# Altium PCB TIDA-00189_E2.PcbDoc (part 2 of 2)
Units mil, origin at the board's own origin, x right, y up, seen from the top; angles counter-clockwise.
Board outline 2350 x 1950 mil, 4 copper layers (Layer 1 - Top Layer, Layer 2 - GND, Layer 3 - Inner Layer, Layer 4 - Bottom Layer), stack 61.4 mil thick; 163 components, 96 nets, 412 pads, 169 vias.
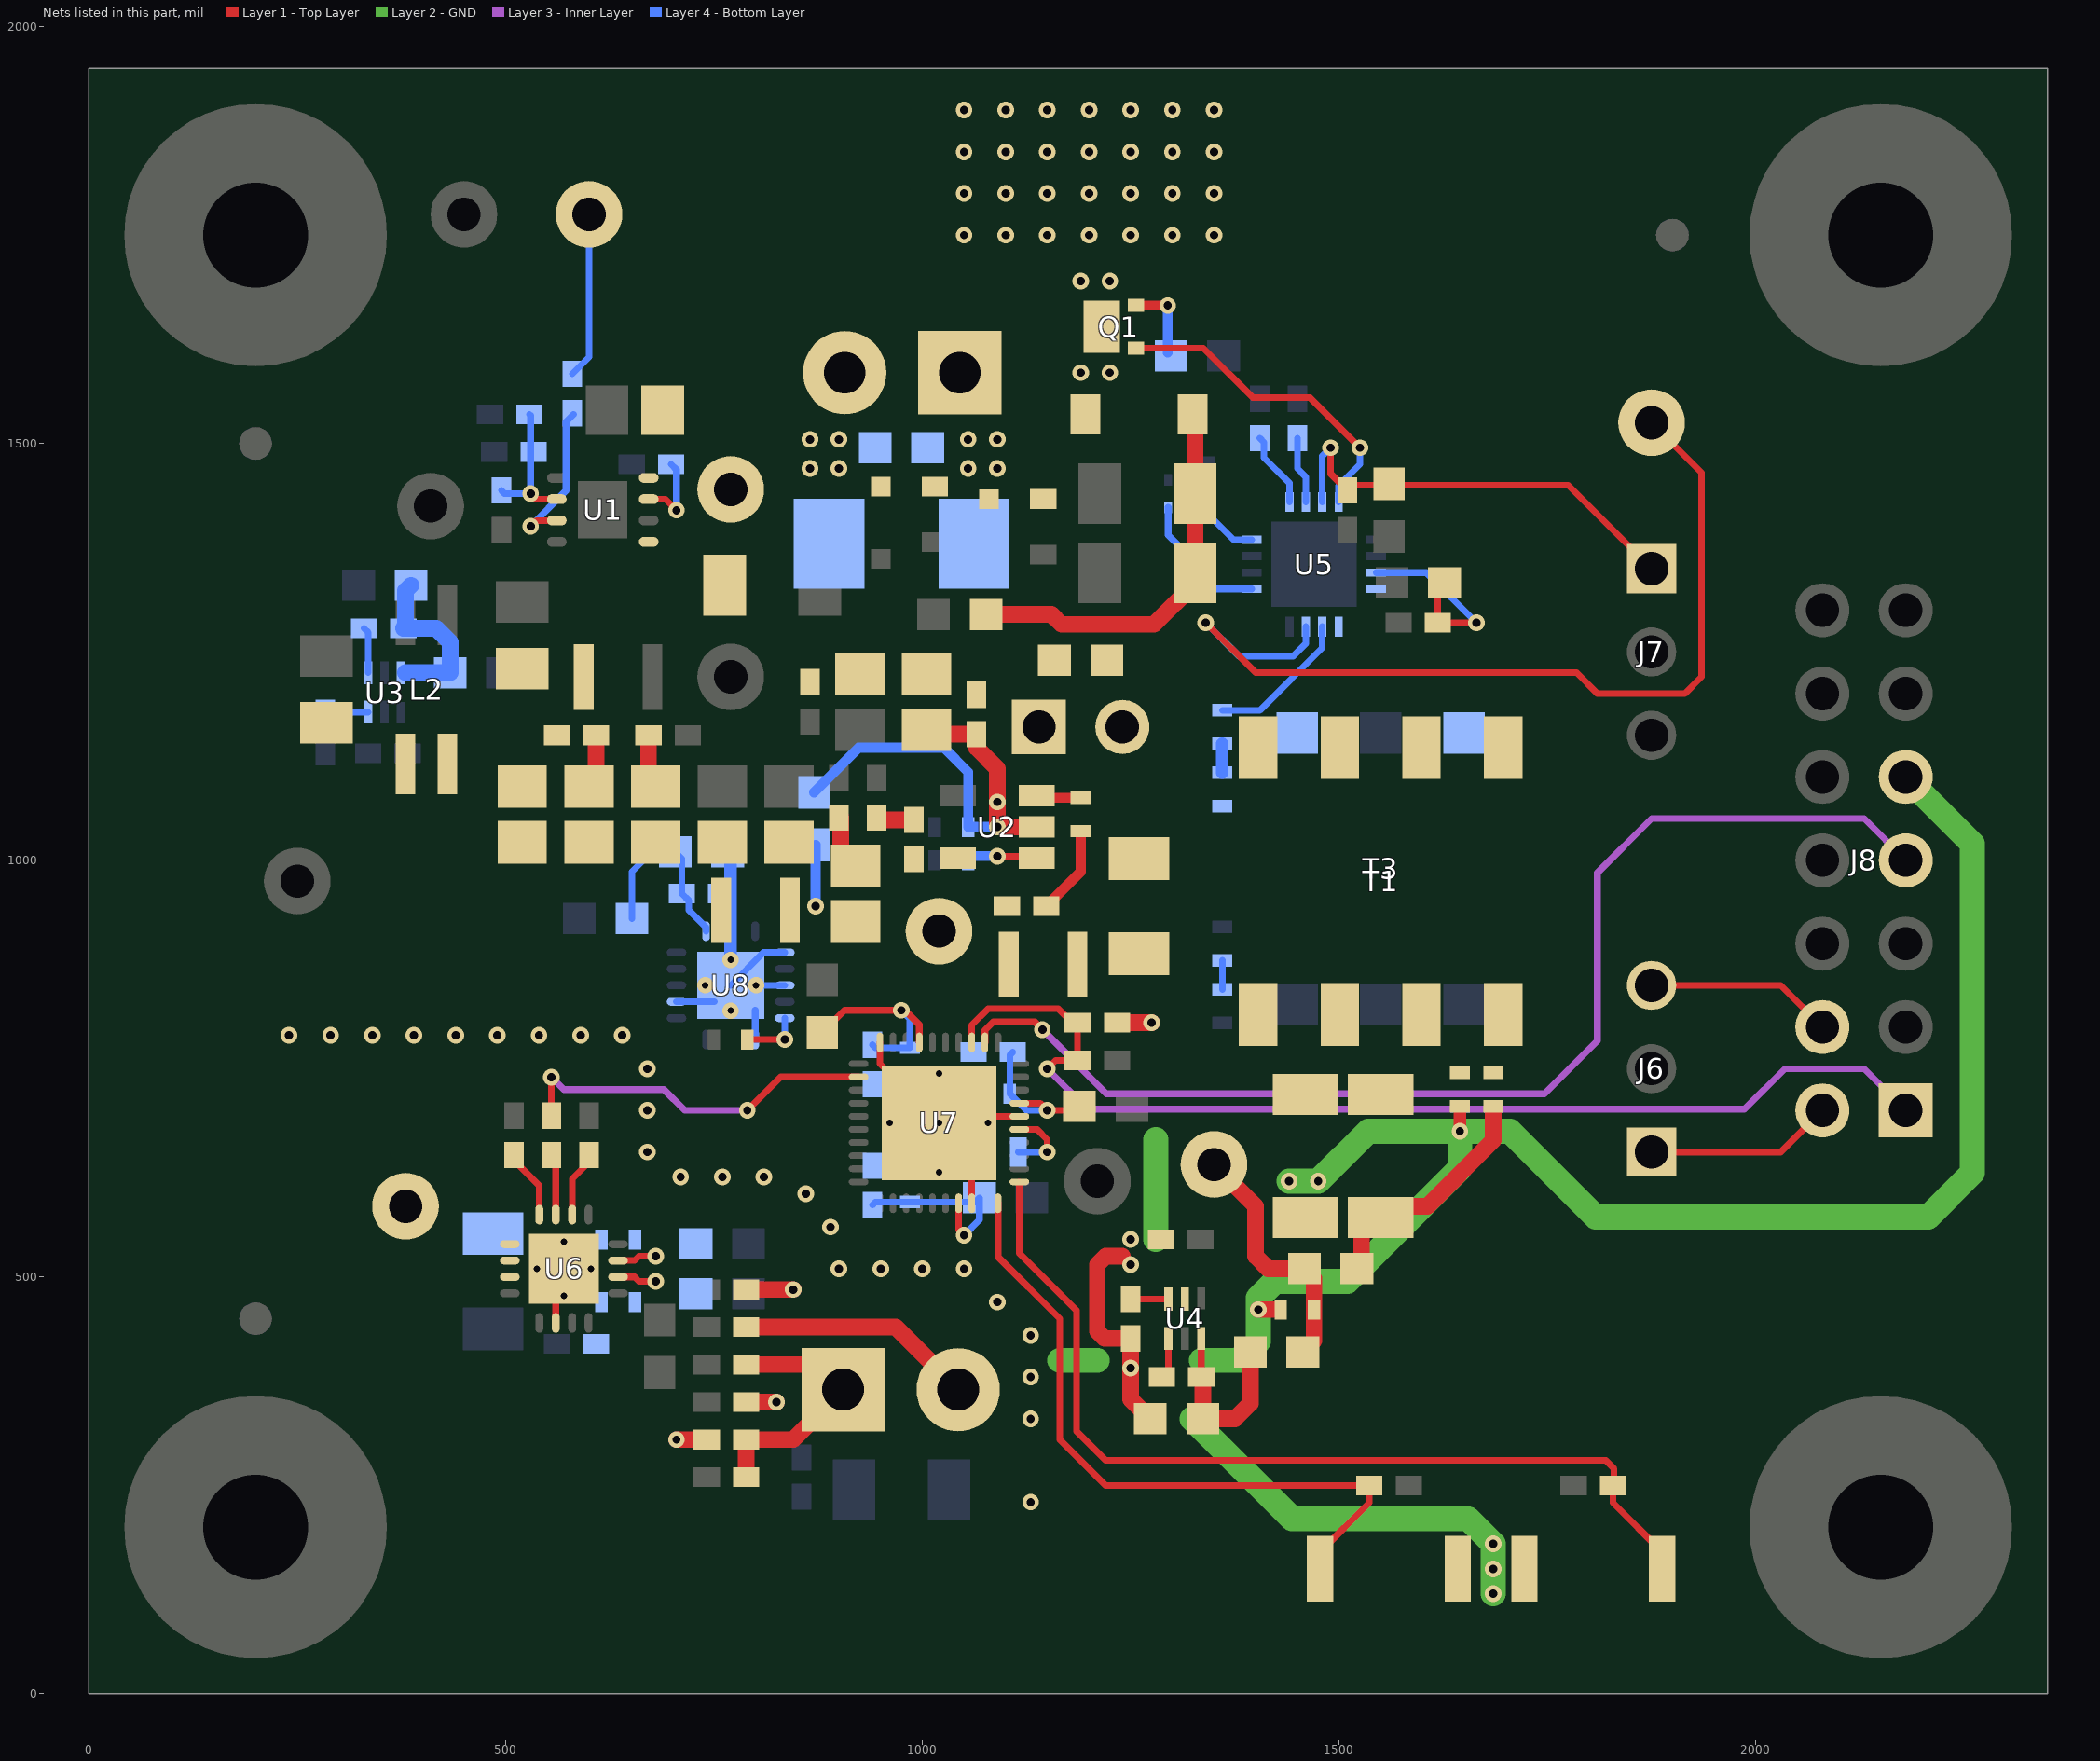
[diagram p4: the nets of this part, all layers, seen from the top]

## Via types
v1: diameter 20, hole 10, Layer 1 - Top Layer to Layer 4 - Bottom Layer, 147 vias
v2: diameter 19.68, hole 7.87, Layer 1 - Top Layer to Layer 4 - Bottom Layer, 22 vias

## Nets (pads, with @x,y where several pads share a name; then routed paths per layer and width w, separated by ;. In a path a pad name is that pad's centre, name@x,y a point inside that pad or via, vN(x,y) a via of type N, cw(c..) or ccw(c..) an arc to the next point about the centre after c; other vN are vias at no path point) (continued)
NetC1_2: C1.2 R4.1 R8.2 U1.2 | length 166.2
  Layer 1 - Top Layer w8: v1(530,1440) 536.76,1433.24 U1.2@561.36,1433.24
  Layer 4 - Bottom Layer w8: R8.2@495,1443.62 498.62,1440 v1(530,1440) 530,1490 530,1533.62 C1.2@528.62,1535
NetC2_1: C2.1 C3.1 C8.1 C9.1 L1.1 L2.3 R2.2
NetC2_2: C2.2 R5.2 | length 65.1
  Layer 1 - Top Layer w20: C2.2@600,1088.46 608.62,1097.09 R5.2@608.62,1150
NetC3_2: C3.2 R6.2 | length 65.1
  Layer 1 - Top Layer w20: R6.2@671.38,1150 671.38,1097.09 C3.2@680,1088.46
NetC4_2: C4.2 R7.2 | length 51.4
  Layer 1 - Top Layer w20: C4.2@902,1000 R7.2@902,1051.38
NetC5_1: C5.1 R1.2 TP1.1 U1.5 U1.8
NetC6_1: C6.1 D1.2 D3.2 D4.1 J1.2
  other v1: 865,1470 900,1470 865,1505 900,1505
NetC6_2: C6.2 D2.2 D3.1 D5.1 J1.1
  other v1: 1055,1470 1090,1470 1055,1505 1090,1505
NetC8_2: C8.2 L2.4 L3.1 R5.1 R9.2
NetC11_1: C11.1 U1.7 | length 96.5
  Layer 1 - Top Layer w8: U1.7@671.6,1433.24 691.76,1433.24 v1(705,1420)
  Layer 4 - Bottom Layer w8: C11.1@698.62,1475 705,1468.62 v1(705,1420)
NetC12_1: C12.1 C16.1 R10.2 R15.2 U2.2 | length 581.2
  Layer 1 - Top Layer w20: C12.1@1005,1156.54 1010.16,1151.38 R10.2@1065,1151.38 1065,1135 1090,1110 v1(1090,1040) U2.2@1137.24,1040
  Layer 4 - Bottom Layer w12: R15.2@870,1081.5 923.5,1135 1025.87,1135 1055,1105.87 C16.1@1055,1040 v1(1090,1040) v1(1090,1070)
NetC12_2: C12.2 C15.1 J2.1 R10.1 R12.2 R13.2
NetC13_1: C13.1 R11.2 | length 107.1
  Layer 1 - Top Layer w12: C13.1@1148.62,945 1190,986.38 R11.2@1190,1035
NetC13_2: C13.2 L4.1 R14.2 TP6.1 U2.5
NetC14_1: C14.1 T1.4
NetC14_2: C14.2 L4.2
NetC17_1: C17.1 U2.1 | length 85.3
  Layer 1 - Top Layer w8: v1(1090,1005) 1134.84,1005 U2.1@1137.24,1002.6
  Layer 4 - Bottom Layer w8: C17.1@1055,1000 C17.1@1060,1005
  Layer 4 - Bottom Layer w12: C17.1@1060,1005 v1(1090,1005)
NetC18_1: C18.1 R14.1 | length 46.1
  Layer 1 - Top Layer w20: C18.1@945,1051.38 947.76,1048.62 R14.1@990,1048.62
NetC19_1: C19.1 D6.1 L5.1 | length 281.2
  Layer 1 - Top Layer w12: D6.1@1527,548.18 D6.1@1550,571.18 D6.1@1563.82,585
  Layer 1 - Top Layer w20: L5.1@1527,510 D6.1@1527,548.18 ; D6.1@1563.82,585 1606,585 1685,664 C19.1@1685,701
NetC19_2: C19.2 C21.1 T1.5
NetC24_1: C24.1 R17.2 R19.2 U3.6 | length 208.6
  Layer 4 - Bottom Layer w20: 380,1225 C24.1@433.5,1225 433.5,1261.5 416.62,1278.38 R19.2@377.32,1278.38 380,1281.06 380,1323.5 R17.2@386.5,1330
NetC25_1: C25.1 R18.2 R20.2 U4.6 | length 223.3
  Layer 1 - Top Layer w8: R20.2@1334.62,380 1334.62,426.32 U4.6@1334.68,426.38
  Layer 1 - Top Layer w20: R20.2@1334.62,380 1336.5,378.13 C25.1@1336.5,330 1375,330 1393.5,348.5 R18.2@1393.5,410
NetC26_1: C26.1 U3.3 | length 51.6
  Layer 4 - Bottom Layer w8: C26.1@283.7,1177 284.46,1177.76 U3.3@335.02,1177.76
NetC27_1: C27.1 U4.3 | length 45.3
  Layer 1 - Top Layer w8: C27.1@1250,473.62 U4.3@1295.32,473.62
NetC30_2: C30.2 R24.2 | length 35
  Layer 4 - Bottom Layer w8: C30.2@1360,845 R24.2@1360,880
NetC31_1: C31.1 C32.1 D8.1 R23.1 | length 476.2
  Layer 1 - Top Layer w20: R23.1@1076.5,1295 1155,1295 1167,1283 1278,1283 1327.09,1332.09 C31.1@1327.09,1345 C32.1@1327.09,1440 D8.1@1327.09,1532.38
NetC33_1: C33.1 R27.1 | length 35
  Layer 4 - Bottom Layer w15: C33.1@1360,1105 R27.1@1360,1140
NetC33_2: C33.2 T3.3 U5.4
NetC34_1: C34.1 U5.12 | length 72.4
  Layer 4 - Bottom Layer w8: C34.1@1340,1421.38 1340,1418 1373.47,1384.53 U5.12@1395.2,1384.53
NetC35_1: C35.1 U5.13 | length 91.3
  Layer 4 - Bottom Layer w8: C35.1@1405,1506.38 1410,1501.38 1410,1483 1440.47,1452.53 U5.13@1440.47,1429.8
NetC36_1: C36.1 U5.14 | length 80.8
  Layer 4 - Bottom Layer w8: C36.1@1450,1506.38 1450,1470 1460.16,1459.84 U5.14@1460.16,1429.8
NetC39_1: C39.1 R28.1 U6.11 | length 47.2
  Layer 1 - Top Layer w8: U6.11@634.96,519.84 654.84,519.84 660,525 v1(680,525)
NetC40_1: C40.1 R29.1 U6.10 | length 47.2
  Layer 1 - Top Layer w8: U6.10@634.96,500.16 654.84,500.16 660,495 v1(680,495)
NetC44_1: C44.1 U7.25 | length 88.6
  Layer 1 - Top Layer w8: U7.25@1116.46,677.13 1137.87,677.13 1150,665 v1(1150,650)
  Layer 4 - Bottom Layer w8: C44.1@1115,650 v1(1150,650)
NetC45_1: C45.1 C46.1 R38.1 U7.37 | length 251.4
  Layer 1 - Top Layer w8: R38.1@880,793.5 906.5,820 v1(975,820) 979,820 996.38,802.62 U7.37@996.38,781.46
  Layer 4 - Bottom Layer w8: C46.1@940,778.62 943.62,775 C45.1@985,775 985,810 v1(975,820)
NetC47_1: C47.1 C48.1 R39.1 U7.27 | length 182.5
  Layer 1 - Top Layer w8: U7.27@1116.46,708.62 1141.38,708.62 v1(1150,700) 1183.5,700 R39.1@1188.5,705
  Layer 4 - Bottom Layer w8: C48.1@1108.62,770 1105,766.38 C47.1@1105,720 1125,700 v1(1150,700)
NetC49_1: C49.1 C50.1 R40.1 U7.17 | length 225.9
  Layer 1 - Top Layer w8: U7.17@1043.62,588.54 1043.62,556.38 v1(1050,550)
  Layer 4 - Bottom Layer w8: C50.1@940,586.38 943.62,590 C49.1@985,590 1063.5,590 R40.1@1068.5,595 1068.5,568.5 v1(1050,550)
NetC51_1: C51.1 C52.1 R42.2 U8.14 | length 228.6
  Layer 4 - Bottom Layer w8: R42.2@651.5,930 651.5,986.5 675,1010 C51.1@703.5,1010 711.38,1002.13 C52.1@711.38,960 720,951.38 720,940 740.48,919.52 U8.14@740.48,914.96
NetD6_2: D6.2 D7.1 T1.8
NetD8_2: D8.2 Q1.3
  other v1: 1190,1585 1225,1585 1190,1695 1225,1695 1050,1750 1100,1750 1150,1750 1200,1750 1250,1750 1300,1750 1350,1750 1050,1800 1100,1800 1150,1800 1200,1800 1250,1800 1300,1800 1350,1800 1050,1850 1100,1850 1150,1850 1200,1850 1250,1850 1300,1850 1350,1850 1050,1900 1100,1900 1150,1900 1200,1900 1250,1900 1300,1900 1350,1900
NetD9_2: D9.2 R26.1 U5.9 | length 168
  Layer 4 - Bottom Layer w8: D9.2@1295,1423.46 1295,1390 1327.09,1357.91 R26.1@1327.09,1345 1346.61,1325.47 U5.9@1395.2,1325.47
NetJ2_2: J2.2 R12.1 T1.1
NetJ3_1: J3.1 R30.1 R36.1 R37.2 | length 315
  Layer 1 - Top Layer w20: R30.1@788.62,260 R37.2@788.62,305 845,305 J3.1@905,365 875,395 R36.1@788.62,395
NetJ3_2: J3.2 R32.1 | length 285.4
  Layer 1 - Top Layer w20: R32.1@788.62,440 968,440 J3.2@1043,365
NetJ6_1: J6.1 J8.2 | length 225.7
  Layer 1 - Top Layer w8: J6.1@1875,650 2030,650 J8.2@2080,700
NetJ6_3: J6.3 J8.4 | length 225.7
  Layer 1 - Top Layer w8: J6.3@1875,850 2030,850 J8.4@2080,800
NetQ1_1: Q1.1 U5.16 | length 393.7
  Layer 1 - Top Layer w8: Q1.1@1256.5,1614.41 1337.24,1614.41 1396.65,1555 1465,1555 v1(1525,1495)
  Layer 4 - Bottom Layer w8: U5.16@1499.53,1429.8 1499.53,1449.53 1525,1475 v1(1525,1495)
NetQ1_2: Q1.2 R25.2 | length 94.4
  Layer 1 - Top Layer w12: Q1.2@1256.5,1665.59 v1(1294.41,1665.59)
  Layer 4 - Bottom Layer w12: R25.2@1294.41,1609.09 v1(1294.41,1665.59)
NetR3_1: R3.1 U1.3 | length 189.5
  Layer 1 - Top Layer w8: v1(530,1400.9) 536.76,1407.65 U1.3@561.36,1407.65
  Layer 4 - Bottom Layer w8: v1(530,1400.9) 572.53,1443.43 572.53,1526.15 R3.1@581.38,1535
NetR3_2: R3.2 TP2.1 | length 199.7
  Layer 4 - Bottom Layer w8: R3.2@580,1583.62 600,1603.62 TP2.1@600,1775
NetR11_1: R11.1 U2.3 | length 53.8
  Layer 1 - Top Layer w12: U2.3@1137.24,1077.4 1139.65,1075 R11.1@1190,1075
NetR19_1: R19.1 U3.4 | length 55.4
  Layer 4 - Bottom Layer w8: R19.1@330.08,1278.38 335.02,1273.44 U3.4@335.02,1225
NetR20_1: R20.1 U4.4 | length 50.1
  Layer 1 - Top Layer w8: R20.1@1286.38,380 1295.32,388.94 U4.4@1295.32,426.38
NetR27_2: R27.2 U5.6 | length 176.2
  Layer 4 - Bottom Layer w8: R27.2@1360,1180 1405,1180 1479.84,1254.84 U5.6@1479.84,1280.2
NetR33_1: R33.1 U6.16 | length 78.5
  Layer 1 - Top Layer w8: R33.1@515.32,643 515.32,634.68 540.47,609.53 U6.16@540.47,574.96
NetR34_1: R34.1 U6.15 | length 68.2
  Layer 1 - Top Layer w8: U6.15@560.16,574.96 R34.1@560.16,643.19
NetR35_1: R35.1 U6.14 | length 81.8
  Layer 1 - Top Layer w8: U6.14@579.84,574.96 579.84,617.84 605,643 R35.1@605,646.38
NetR44_1: R44.1 U8.6 | length 70.6
  Layer 1 - Top Layer w8: R44.1@790,785 v1(835,785)
  Layer 4 - Bottom Layer w8: U8.6@834.96,810.63 v1(835,785) v1(835,785)
NetT1_2: T1.2 T1.3
NetT1_6: T1.6 T1.7
NetT3_1: T3.1 U5.5
NetTP11_1: TP11.1 U5.7 | length 1131.4
  Layer 1 - Top Layer w8: v1(1340,1285) 1400,1225 1785,1225 1810,1200 1915,1200 1935,1220 1935,1465 TP11.1@1875,1525
  Layer 4 - Bottom Layer w8: v1(1340,1285) 1380,1245 1445,1245 1460.16,1260.16 U5.7@1460.16,1280.2
REFN0: C20.2 C21.2 C23.2 C25.2 C27.2 C37.1 C38.1 C39.2 C40.2 C42.2 C44.2 C45.2 C46.2 C47.2 C48.2 C49.2 C50.2 C51.2 C52.2 C53.2 D7.2 J8.9 R31.2 R37.1 S1.1 S2.1 TP5.1 U4.2 U6.1 U6.2 U6.3 U6.6 U6.17 U7.18 U7.26 U7.40 U7.41 U8.2 U8.4 U8.7 U8.10 U8.15 | length 3786.9
  Layer 1 - Top Layer w8: U6.6@560.16,445.04 U6.17@560.16,500.16 ; U7.40@949.13,781.46 949.13,755.87 v2(1020,685) ; U7.18@1059.37,588.54 1059.37,645.63 v2(1020,685) ; U7.26@1116.46,692.87 1039.01,692.87 ccw(c1039.01,665.99) v2(1020,685)
  Layer 1 - Top Layer w12: D7.2@1460,571.18 1468.82,571.18 D7.2@1485,555
  Layer 1 - Top Layer w15: v1(1645,675) C21.2@1645,705
  Layer 1 - Top Layer w20: v1(705,305) R37.1@741.38,305 ; C42.2@788.62,350 v1(825,350) ; C38.1@788.62,485 v1(845,485) ; C53.2@1233.62,805 v1(1275,805) ; 1240,525 1220,525 1210,515 1210,435 1218.62,426.38 C27.2@1250,426.38 1250,353.5 C25.2@1273.5,330 ; v1(1403,461) C20.2@1425,461
  Layer 2 - GND w30: 1165,400 1210,400 ; 1280,545 1280,665 ; 1323.7,330 1443.7,210 1655,210 v1(1685,180) v1(1685,120) ; 1335,400 1380,400 1403,423 1403,475 1423,495 1510,495 1645,630 v1(1645,675) ; v1(1440,615) v1(1475,615) 1535,675 v1(1645,675) ; J8.9@2180,1100 2260,1020 2260,625 2207,572 1808,572 1705,675 v1(1645,675)
  Layer 4 - Bottom Layer w8: U8.10@705.04,830.31 U8.15@750.32,830.31 ; U8.15@770,850 809.37,889.37 U8.2@834.96,889.37 ; U8.7@799.53,785.04 U8.15@799.53,820.47 ; v2(800.51,850) U8.4@834.96,850
  Layer 4 - Bottom Layer w15: v2(770,880.51) 770,1000.57 C51.2@779.43,1010
  other v1: 1685,150 1130,230 1130,330 1130,380 1250,391 1130,430 1090,470 900,510 950,510 1000,510 1050,510 1250,515 1250,545 890,560 860,600 710,620 760,620 810,620 670,650 670,700 670,750 240,790 290,790 340,790 390,790 440,790 490,790 540,790 590,790 640,790
  other v2: 570,477.72 537.72,510 602.28,510 570,542.28 1020,625.94 960.94,685 1079.06,685 1020,744.06 770,819.49 739.49,850
SBWTCK: J8.7 U7.32 | length 1434.8
  Layer 1 - Top Layer w8: U7.32@1075.12,781.46 1075.12,796.2 1084.92,806 1135,806 v1(1144,797)
  Layer 3 - Inner Layer w8: v1(1144,797) 1221,720 1746.57,720 1810,783.43 1810,985 1875,1050 2130,1050 J8.7@2180,1000
SBWTDIO: C53.1 J8.1 R43.1 U7.33 | length 1339.5
  Layer 1 - Top Layer w8: U7.33@1059.37,781.46 1059.37,802.37 1079,822 1163,822 1180,805 C53.1@1186.38,805 R43.1@1186.38,760 1160,760 v1(1150,750)
  Layer 3 - Inner Layer w8: v1(1150,750) 1198.5,701.5 1986.5,701.5 2035,750 2130,750 J8.1@2180,700
SCLK_ADC: R34.2 U7.2 | length 453.1
  Layer 1 - Top Layer w8: v1(555,739.98) R34.2@555,693.62 R34.2@560,693.6 ; v1(790,700) 830.12,740.12 U7.2@923.54,740.12
  Layer 3 - Inner Layer w8: v1(555,739.98) 569.98,725 690,725 715,700 v1(790,700)
SW1: R41.1 S1.2 U7.20 | length 832.9
  Layer 1 - Top Layer w8: U7.20@1090.87,588.54 1090.87,524.13 1165,450 1165,305 1220,250 R41.1@1536.38,250 1536.38,229.38 1477.32,170.32 S1.2@1477.32,150
SW2: R46.1 S2.2 U7.21 | length 1136.2
  Layer 1 - Top Layer w8: U7.21@1116.46,614.13 1116.46,528.54 1185,460 1185,315 1220,280 1820,280 1830,270 1830,251.38 R46.1@1828.62,250 1828.62,229.38 1887.68,170.32 S2.2@1887.68,150
V2: C4.1 C10.1 L1.2 R15.1 | length 73.5
  Layer 4 - Bottom Layer w12: v1(872,945) R15.1@872,1018.5
V3: C20.1 L5.2 R18.1 TP8.1 | length 305.8
  Layer 1 - Top Layer w20: TP8.1@1350,635 1400,585 1400,525 1415,510 L5.2@1458.5,510 1470,498.5 1470,465 1470,423.5 R18.1@1456.5,410
VA: C29.1 J7.1 R22.1 U5.15 | length 538.1
  Layer 1 - Top Layer w8: v1(1490,1495) 1490,1463.62 C29.1@1510,1443.62 1516.38,1450 1560,1450 1775,1450 J7.1@1875,1350
  Layer 4 - Bottom Layer w8: U5.15@1479.84,1429.8 1479.84,1484.84 v1(1490,1495)
VD: C28.1 R21.1 U5.3 | length 249.8
  Layer 1 - Top Layer w8: R21.1@1626.5,1340 1618.62,1332.13 C28.1@1618.62,1285 v1(1665,1285)
  Layer 4 - Bottom Layer w8: U5.3@1544.8,1345.16 1604.84,1345.16 v1(1665,1285)
pads on no net: FID1.1 FID2.1 FID3.1 FID4.1 FID5.1 FID6.1 H1.1 H2.1 H3.1 H4.1 J8.3 J8.5 J8.6 J8.8 J8.10 J8.11 J8.13 SH-J2.0 SH-J3.0 T3.2 T3.5 U1.6 U3.5 U4.5 U5.11 U7.6 U7.7 U7.8 U7.9 U7.10 U7.11 U7.15 U7.16 U7.19 U7.22 U7.23 U7.24 U7.28 U7.29 U7.30 U7.31 U7.34 U7.38 U7.39

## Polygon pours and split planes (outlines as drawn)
REFN0 on Layer 2 - GND "Layer 2 - GND- REFN0" (solid, remove dead copper, pour order 2): 1150,370 1165,385 1165,415 1150,430 1150,455 1080,525 925,525 910,540 910,580 850,640 710,640 690,660 690,780 660,810 230,810 230,755 335,650 335,485 625,195 1150,195
REFN0 on Layer 2 - GND "Layer 2 - GND-REFN0 2" (solid, remove dead copper, pour order 4): 1265,665 1295,665 1320,690 1320,760 1320,815 1280,855 985,855 935,905 720,905 720,830 755,795 850,700 880,700 905,700 940,665 940,605 970,575 1040,575 1115,650 1135,670 1160,670 1175,670 1195,690 1220,690 1240,690 1265,665
GND on Layer 2 - GND "Layer 2 - GND- GND" (solid, remove dead copper, pour order 6): 370,940 750,940 795,985 1050,985 1100,935 1925,935 1925,1180 1885,1180 1435,1630 1150,1630 1085,1695 925,1695 780,1840 390,1840 390,1545 170,1325 170,1140

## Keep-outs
Keep-Out Layer:
  text ".Layer_Name" at 577,-858.49 h60

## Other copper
Layer 1 - Top Layer:
  region net REFN0: 1110,210 1150,210 1150,440 1060,530 920,530 910,540 910,580 850,640 710,640 690,660 690,780 660,810 200,810 200,770 630,770 650,750 650,640 690,600 830,600 870,560 870,510 890,490 1040,490 1110,420
  region net AIN2: 585,457 585,395 570,380 550,380 535,395 535,457 545,457 545,429 554,420 566,420 575,429 575,457
  region net REFN0: 528,490 523,495 375,495 330,540 330,630 450,630 528,552
  region net NetC2_1: 790,1050 790,995 775,980 775,900 410,900 250,1060 250,1190 320,1190 320,1165 330,1155 395,1155 395,1080 425,1050
  region net NetC8_2: 550,1060 550,1115 570,1135 580,1135 580,1170 590,1180 610,1180 610,1260 485,1260 485,1175 465,1155 415,1155 415,1080 435,1060
  region net GND2: 730,1060 730,1120 715,1135 700,1135 700,1170 690,1180 660,1180 660,1265 795,1265 825,1235 825,1200 840,1185 960,1185 960,1125 970,1115 1045,1115 1065,1095 1065,1060 1020,1060 1020,1070 1010,1080 880,1080 870,1070 870,1060
  region net V2: 825,900 825,980 810,995 810,1050 870,1050 870,970 885,955 950,955 950,900
  region net NetC13_2: 1120,835 1065,835 1060,840 1015,840 975,880 975,1020 1065,1020 1065,980 1080,965 1120,965
  region net NetC12_2: 850,1195 1040,1195 1055,1180 1085,1180 1105,1160 1105,1125 1180,1125 1180,1260 880,1260 850,1230
  region net LOOP_P: 1035,1275 848.23,1275 848.23,1395 1035,1395
  region net NetC5_1: 815,1285 660,1285 660,1390 710,1390 730,1410 730,1430 710,1450 660,1450 660,1570 715,1570 815,1470
  region net GND: 415,1255 455,1255 455,1270 470,1285 650,1285 650,1570 585,1570 585,1400 575,1390 555,1390 545,1380 515,1380 507,1388 507,1413 478,1413 415,1350
  region net NetJ2_2: 1200,1260 1200,1095 1430,1095 1430,1170 1340,1260
  region net NetC14_2: 1170,835 1300,835 1300,915 1170,915
  region net NetC14_1: 1220,975 1670,975 1725,1030 1725,1175 1665,1175 1665,1090 1630,1055 1220,1055
  region net 4V7: 250,1220 320,1220 320,1245 330,1255 395,1255 395,1350 470,1425 507,1425 507,1451 516,1460 542,1460 549,1453 573,1453 573,1487 550,1510 435,1510 320,1395 320,1345 250,1275
  region net LOOP_M: 1065,1330 1160,1330 1185,1305 1270,1305 1270,1480 1185,1480 1185,1410 1170,1395 1065,1395
  region net NetD8_2: 1175,1505 1237,1505 1237,1685 1282,1730 1375,1730 1400,1755 1400,1920 1000,1920 1000,1755 1025,1730 1130,1730 1175,1685
  region net NetT1_2: 1475,1095 1625,1095 1625,1175 1475,1175
  region net NetT1_6: 1475,774.92 1625,774.92 1625,854.92 1475,854.92
  region net NetD6_2: 1595,690 1410,690 1375,725 1375,855 1430,855 1430,770 1455,745 1595,745
  region net NetC19_2: 1630,735 1700,735 1725,760 1725,855 1670,855 1670,795 1630,755
  region net ISO3V3: 1380,455 1380,535 1350,565 1315,565 1315,535 1330,520 1330,455
  region net REFN0: 1420,545 1420,630 1500,630 1500,545
  region net REFN0: 1625,105 1740,105 1740,195 1625,195
  region net NetC6_2: 995,1420 1105,1420 1105,1520 995,1520
  region net NetC6_1: 1125,1420 1125,1640 1100,1665 855,1665 830,1640 830,1550 860,1520 930,1520 970,1480 970,1435 875,1435 785,1525 785,1655 840,1710 1115,1710 1165,1660 1165,1420
  region net REFN0: 1320,459 1320,511 1302,529 1302,557 1247,557 1225,535 1225,520 1245,500 1305,500 1310,495 1310,459
  text ".Layer_Name" at 577,-858.49 h60
Layer 3 - Inner Layer:
  region net NetD8_2: 1175,1505 1237,1505 1237,1685 1282,1730 1375,1730 1400,1755 1400,1920 1000,1920 1000,1755 1025,1730 1130,1730 1175,1685
  text ".Layer_Name" at 575,-853 h60
Layer 2 - GND:
  region net REFN0: 1265,580 1295,580 1345,530 1345,425 1355,415 1355,385 1345,375 1345,310 1245,310 1200,355 1200,375 1190,385 1190,415 1200,425 1200,515
  text ".Layer_Name" at 575,-853 h60
Layer 4 - Bottom Layer:
  region net GND2: 1030,985 1029.41,985.59 905,985.59 905,1085 930,1110 1010,1110 1030,1090
  region net NetC39_1: 645,560 750,560 750,515 660,515 645,530
  region net NetC40_1: 645,455 750,455 750,505 660,505 645,490
  region net REFN0: 1110,210 1150,210 1150,440 1060,530 920,530 910,540 910,580 850,640 710,640 690,660 690,780 660,810 200,810 200,770 630,770 650,750 650,640 690,600 830,600 870,560 870,510 890,490 1040,490 1110,420
  region net NetC6_2: 985,1640 1130,1640 1130,1280 1025,1280 985,1320
  region net NetC6_1: 967,1640 825,1640 825,1280 930,1280 967,1317
  region net LOOP_M: 1185,1305 1270,1305 1270,1425 1185,1425
  region net NetD8_2: 1175,1505 1237,1505 1237,1685 1282,1730 1375,1730 1400,1755 1400,1920 1000,1920 1000,1755 1025,1730 1130,1730 1175,1685
  region net NetC33_2: 1680,1105 1680,1211 1560,1331 1532,1331 1532,1258 1610,1180 1610,1125 1565,1080 1345,1080 1345,1030 1605,1030
  region net NetT3_1: 1510,1293 1510,1150 1485,1125 1420,1125 1420,1175 1494,1249 1494,1293
  region net GND: 1340,1625 1410,1625 1465,1570 1465,1535 1390,1535 1340,1585
  region net 3V3: 369,1196 369,1143 366,1140 366,1116 399,1116 399,1175 378,1196
  region net REFN0: 925,750 1005,750 1040,785 1080,785 1080,700 1090,690 1090,680 1080,670 1080,645 1065,630 1045,630 1030,615 925,615
  region net REFN0: 625,405 625,560 560,560 490,630 330,630 330,540 375,495 535,495 590,440 590,405
  text ".Layer_Name" at 577,-858.49 h60

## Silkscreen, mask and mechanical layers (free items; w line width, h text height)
Top Overlay:
  circle w10: c975,975 r794
  text "TIDA-00189" at 360,910 h50
  text "Rev. E1" at 360,860 h50
  text ".Layer_Name" at 577,-858.49 h60
Bottom Overlay:
  circle w10: c975,975 r794
  text ".Layer_Name" at 577,-858.49 h60
Top Paste:
  text ".Layer_Name" at 577,-858.49 h60
Bottom Paste:
  text ".Layer_Name" at 577,-858.49 h60
Top Solder:
  text ".Layer_Name" at 577,-858.49 h60
  text ".Layer_Name" at 577,-858.49 h60
Bottom Solder:
  text ".Layer_Name" at 577,-858.49 h60
Drill Guide:
  text ".Layer_Name" at 577,-858.49 h60
M1 Board Outline:
  circle w10: c975,975 r794
  lines w10: 0,0 2350,0 2350,1950 0,1950 0,0
  text ".Layer_Name" at 577,-858.49 h60
M2 Board Dimensions:
  rectangle: -0.5,-285.5 124.5,-160.5
  rectangle: 124.5,-410.5 499.5,-285.5
  lines w7: -0.5,-285.5 999.5,-285.5 ; 124.5,-410.5 124.5,-160.5 ; 249.5,-410.5 249.5,-160.5 ; 499.5,-410.5 499.5,-160.5 ; 749.5,-410.5 749.5,-160.5 ; -0.5,-410.5 999.5,-410.5 999.5,-160.5 -0.5,-160.5 -0.5,-410.5
  lines w10: -0.5,-475.5 -0.5,-455.5 ; 59.5,-485.5 -0.5,-465.5 ; 59.5,-445.5 -0.5,-465.5 ; 223.58,-465.5 -0.5,-465.5 ; 775.42,-465.5 999.5,-465.5 ; 939.5,-485.5 999.5,-465.5 ; 939.5,-445.5 999.5,-465.5 ; 999.5,-475.5 999.5,-455.5
  text "1000 (mil)" at 233.58,-501.49 h60
  text ".Layer_Name" at 577,-858.49 h60
M3 3D STEP Top:
  text ".Layer_Name" at 577,-858.49 h60
M4 3D STEP Bottom:
  text ".Layer_Name" at 577,-858.49 h60
M5 Assembly Top:
  lines w10: -292,-930.17 6308,-930.17 ; -292,-726.83 6310,-726.83 ; -292,-523.5 -292,-1133.5 3713,-1133.5 6310,-1133.5 6310,-523.5 -291.5,-523.5 -291.5,-1133.5 1284,-1133.5 ; 2173,-1133.5 2173,-523.5 ; 3440,-726.83 3440,-523.5 ; 4280,-726.83 4280,-523.5 ; 4902,-1140 4902,-937.17
  text "COMPONENTS MARKED 'DNP' SHOULD NOT BE POPULATED." at 1153.5,-318.5 h60
  text "ASSEMBLY VARIANT:" at 1153,-434 h60
  text ".VariantName" at 2189,-434 h60
  text "PCB VIEWED FROM TOP SIDE" at -228.5,-655.67 h60
  text "BOARD #:" at 2248,-655.67 h60
  text ".PRJ_Number" at 2793.5,-655.67 h60
  text "REV:" at 3638,-655.67 h60
  text ".PCB_Rev" at 3929.5,-655.67 h60
  text "SVN REV:" at 4476,-655.67 h60
  text ".VersionControl_RevNumber" at 4982,-655.67 h60
  text "IGNORE ->" at -228.5,-858.49 h60
  text "PLOT NAME =" at -228.5,-1064.34 h60
  text ".plot_File_Name" at 577,-1064.34 h60
  text "GENERATED    :" at 2250,-1064.34 h60
  text ".Print_Date" at 3119.5,-1064.34 h60
  text ".Print_Time" at 3848.5,-1064.34 h60
  text "TEXAS INSTRUMENTS" at 5113,-1064.34 h60
M6 Assembly Bottom:
  lines w10: -292.5,-727.33 6309.5,-727.33 ; -290.5,-930.67 6309.5,-930.67 ; 1115.5,-1140.5 1115.5,-937.67 ; 1737.5,-727.33 1737.5,-524 ; 2577.5,-727.33 2577.5,-524 ; 3844.5,-1134 3844.5,-524 ; 4733.5,-1134 6309,-1134 6309,-524 -292.5,-524 -292.5,-1134 2304.5,-1134 6309.5,-1134 6309.5,-524
  text "COMPONENTS MARKED 'DNP' SHOULD NOT BE POPULATED." at 6102,-318 h60
  text ".VariantName" at 5058,-434 h60
  text "ASSEMBLY VARIANT:" at 6097,-434 h60
  text ".VersionControl_RevNumber" at 1035.5,-656.17 h60
  text "SVN REV:" at 1541.5,-656.17 h60
  text ".PCB_Rev" at 2088,-656.17 h60
  text "REV:" at 2379.5,-656.17 h60
  text ".PRJ_Number" at 3224,-656.17 h60
  text "BOARD #:" at 3769.5,-656.17 h60
  text "PCB VIEWED FROM BOTTOM SIDE" at 6246,-656.17 h60
  text "IGNORE ->" at 2547.85,-858.49 h60
  text "TEXAS INSTRUMENTS" at 904.5,-1064.84 h60
  text ".Print_Time" at 2169,-1064.84 h60
  text ".Print_Date" at 2898,-1064.84 h60
  text "GENERATED    :" at 3767.5,-1064.84 h60
  text ".plot_File_Name" at 5440.5,-1064.84 h60
  text "PLOT NAME =" at 6246,-1064.84 h60
M9 Title Sheet:
  drawing of 57 lines, arcs and shapes, not listed
  text "1" at 739.84,8036.5 h70
  text "2" at 3235.5,8036.5 h70
  text "3" at 5724.84,8036.5 h70
  text "4" at 8231.51,8036.5 h70
  text "5" at 10730.5,8036.5 h70
  text "6" at 13235.5,8036.5 h70
  text "A" at -416.5,6893.5 h70
  text "A" at 14383.5,6893.5 h70
  text "B" at -416.5,4513.5 h70
  text "B" at 14383.5,4513.5 h70
  text "C" at -416.5,2138.5 h70
  text "C" at 14383.5,2138.5 h70
  text "PROJECT TITLE:" at 11343.5,277.5 h45
  text ".PRJ_Title" at 11393.5,144.17 h70
  text "DESIGNED FOR:" at 11343.5,-23.5 h45
  text ".PRJ_Customer" at 11393.5,-163.5 h70
  text "D" at -416.5,-231.5 h70
  text "D" at 14383.5,-231.5 h70
  text "FILE NAME:" at 11343.5,-323.5 h45
  text ".PCB_File_Name_No_Path" at 11393.5,-443.5 h70
  text "Texas Instruments (TI) and/or its licensors do not warrant the accuracy or completeness of this specification" at 6374,-605.34 h45
  text "ENGINEER:" at 11343.5,-613.5 h45
  text "LAYOUT BY:" at 12848.5,-613.5 h45
  text "or any information contained therein. TI and/or its licensors do not warrant that this design will meet" at 6329.01,-718 h45
  text ".PRJ_Engineer" at 11393.5,-768.49 h70
  text ".PCB_Layout" at 12899,-768.49 h70
  text "the specifications, will be suitable for your application or fit for any particular purpose, or will operate in" at 6329.01,-830.67 h45
  text ".Layer_Name" at 577,-858.49 h60
  text "ALTIUM DESIGNER VERSION:" at 12848.5,-923.5 h45
  text "an implementation. TI and/or its licensors do not warrant that the design is production worthy. You should" at 6329.01,-943.33 h45
  text "completely validate and test your design implementation to confirm the system functionality for your application." at 6374,-1056 h45
  text ".print_Scale" at 11393.5,-1056.83 h70
  text ".Application_BuildNumber" at 12899,-1056.83 h70
  text "1" at 739.84,-1263.5 h70
  text "2" at 3235.5,-1263.5 h70
  text "3" at 5724.84,-1263.5 h70
  text "4" at 8231.51,-1263.5 h70
  text "5" at 10730.5,-1263.5 h70
  text "6" at 13235.5,-1263.5 h70
M10 Fab Notes:
  drawing of 212 lines, arcs and shapes, not listed
  text "DESIGN INFORMATION" at 12381.02,6810 h60
  text "(REFER ALSO ARRAY/PANEL PROFILING INFORMATION)" at 12019.46,6648.29 h60
  text "BOARD SIZE" at 11333.46,6644 h60
  text "1950MIL" at 11795.78,6516.18 h60
  text "X" at 12301.46,6516.18 h60
  text "2350MIL" at 12532.78,6516.18 h60
  text "Number of Layers :" at 11736.46,6319 h60
  text "4" at 12831.27,6309 h60
  text "MIN. TRACK WIDTH:" at 11736.46,6180 h60
  text "8" at 12832.7,6180 h60
  text "MIL" at 12987.46,6180 h60
  text "MIN. CLEARANCE:" at 11736.46,6048 h60
  text "MIL" at 12987.46,6048 h60
  text "7.5" at 12780,6045 h60
  text "MIN. VIA PAD SIZE:" at 11736.46,5916 h60
  text "20" at 12802.71,5916 h60
  text "MIL" at 12987.46,5916 h60
  text "0.05mm (2MIL)" at 12431.46,5774.29 h60
  text "MINIMUM ANNULAR RING" at 11407.23,5770 h60
  text "EXTERNAL" at 13139.46,5770 h60
  text "PER" at 11607.23,5652 h60
  text "IPC-D-275 CLASS 2 LEVEL C" at 11827.23,5652 h60
  text "MIL, HOLES" at 13315.46,5539.71 h60
  text "+/-" at 12923,5539 h60
  text "+/-" at 13777,5539 h60
  text "REGISTRATION TOLERANCES:" at 11407.23,5534 h60
  text "METAL" at 12607,5534 h60
  text "5" at 13183.2,5534 h60
  text "3" at 14016.2,5534 h60
  text "MIL" at 14132.46,5534 h60
  text "MATERIAL:" at 11332.46,5324.54 h60
  text "FR-4 High Tg" at 12318.9,5184.21 h60
  text "FR-408" at 11753.46,5175.64 h60
  text "X" at 12165.46,5175.64 h60
  text "OTHER" at 13241.46,5175.64 h60
  text "62 MIL (1.6mm) +/-10%" at 12073.56,5012.92 h60
  text "THICKNESS:" at 11407.23,5008.64 h60
  text "X" at 11945.4,5008.64 h60
  text "OTHER" at 13358.46,5008.64 h60
  text "TOLERANCE:" at 11407.23,4850.64 h60
  text "X" at 12246.53,4850.64 h60
  text "ANSI IPC-6012 TYPE 3 CLASS 2" at 12433.48,4850.64 h60
  text "OTHER +/-" at 12433.46,4694.64 h60
  text "BOW & TWIST:" at 11407.23,4537.64 h60
  text "X" at 12246.53,4537.64 h60
  text "ANSI IPC-6012 TYPE 3 CLASS 2" at 12433.48,4537.64 h60
  text "OTHER +/-" at 12433.46,4379.13 h60
  text "COPPER THICKNESS (FINISHED):" at 11332.46,4243.64 h60
  text "1.4MIL (1oz)" at 12212.46,4090.92 h60
  text "2MIL (1.4oz)" at 12979.46,4090.92 h60
  text "2.8MIL (2oz)" at 13706.46,4090.92 h60
  text "OUTER:" at 11689.46,4086.64 h60
  text "X" at 12084,4086 h60
  text "1.4MIL (1oz)" at 12212.46,3933.92 h60
  text "2.8MIL (2oz)" at 12979.46,3933.92 h60
  text "N/A" at 13706,3934.29 h60
  text "INNER SIGNAL:" at 11400.38,3929.64 h60
  text "X" at 12085.42,3929.64 h60
  text "DRILLING:" at 11332.46,3790.64 h60
  text "REFERENCE:" at 11407.23,3673.64 h60
  text "X" at 12055.46,3673.64 h60
  text "AS SHOWN" at 12242.46,3673.64 h60
  text "X" at 12956.46,3673.64 h60
  text "NC_DRILL FILES" at 13093.46,3673.64 h60
  text "PTH MIN COPPER THICKNESS:" at 11407.23,3515.64 h60
  text "X" at 12757.46,3515.64 h60
  text "1MIL" at 12894.46,3515.64 h60
  text "OTHER" at 13391.46,3515.64 h60
  text "BOARD FINISH:" at 11332.46,3356.64 h60
  text "SILKSCREEN:" at 11487.68,3238.64 h60
  text "X" at 12436.46,3238.64 h60
  text "TOP" at 12562.46,3238.64 h60
  text "X" at 12946.46,3238.64 h60
  text "BOTTOM" at 13073.46,3238.64 h60
  text "SILKSCREEN COLOR:" at 11487.68,3071.64 h60
  text "X" at 12435.42,3071.64 h60
  text "WHITE" at 12562.46,3071.64 h60
  text "OTHER" at 13073.46,3071.64 h60
  text "SOLDER RESIST COLOR:" at 11487.68,2901.64 h60
  text "X" at 12055.42,2742.44 h60
  text "GREEN" at 12182.46,2742.44 h60
  text "BLUE" at 12773.46,2742.44 h60
  text "OTHER" at 13311.46,2742.44 h60
  text "IMMERSION GOLD (ENIG)" at 12393.46,2553.92 h60
  text "ENEPIG" at 13731,2550.64 h60
  text "SURFACE FINISH:" at 11332.46,2549.64 h60
  text "X" at 12206.51,2549.64 h60
  text "IMM. TIN/SILVER OR EQUIV" at 11662,2392.64 h60
  text "OTHER" at 13093.46,2392.64 h60
  text "ARRAY/PANEL:" at 11332.46,2213.64 h60
  text "CUT AND TRIM PER MECH LAYER 1" at 12393.46,2209.35 h60
  text "N.C. ROUTE" at 12393.46,2057.64 h60
  text "X" at 13072.46,2057.64 h60
  text "V. SCORE" at 13259.46,2057.64 h60
  text "CERTIFICATION:" at 11332.46,1920.64 h60
  text "MATERIALS AND WORKMANSHIP FOR ALL PCBS" at 12057.46,1920.64 h60
  text "TO MEET OR EXCEED THE REQUIREMENTS OF:" at 12057.46,1822.64 h60
  text "X" at 11683.96,1686.13 h60
  text "ANSI IPC-A-600F CLASS ->" at 11822.96,1686.13 h60
  text "X" at 13462.02,1686.13 h60
  text "2" at 13580.96,1686.14 h60
  text "1" at 13265.96,1684.64 h60
  text "3" at 13934.96,1684.64 h60
  text "X" at 11686.02,1526.64 h60
  text "UL 94V-0" at 11822.96,1526.64 h60
  text "X" at 12498.02,1526.64 h60
  text "RoHS" at 12634.96,1526.64 h60
  text "OTHER" at 13279.36,1526.64 h60
  text "PER ORDER" at 13676.42,1526.64 h60
  text "ADDITIONAL REQUIREMENTS:" at 11332.46,1385.64 h60
  text "MICROSECTION:" at 11407.23,1270.64 h60
  text "YES" at 12312.96,1270.64 h60
  text "REQUIRED" at 13174.46,1114.49 h60
  text "BARE BOARD ELEC. TEST:" at 11407.23,1111.64 h60
  text "NONE" at 12712.96,1111.64 h60
  text "X" at 13047.46,1111.64 h60
  text "PER ORDER" at 13766.46,1111.64 h60
  text "MANUFACTURER'S UL:" at 11407.23,954.64 h60
  text "RAIL" at 12572.96,950.35 h60
  text "METAL" at 13064.77,950.35 h60
  text "X" at 13440,950 h60
  text "SILK" at 13576.46,950.35 h60
  text ".Layer_Name" at 577,-858.49 h60
M11 Gerber Information:
  lines w10: -292,-930.17 6308,-930.17 ; -292,-726.83 6310,-726.83 ; -292,-523.5 -292,-1133.5 3713,-1133.5 6310,-1133.5 6310,-523.5 -291.5,-523.5 -291.5,-1133.5 1284,-1133.5 ; 2173,-1133.5 2173,-523.5 ; 3440,-726.83 3440,-523.5 ; 4280,-726.83 4280,-523.5 ; 4902,-1140 4902,-937.17
  text "ALL ARTWORK VIEWED FROM TOP SIDE" at -228.5,-655.67 h60
  text "BOARD #:" at 2248,-655.67 h60
  text ".PRJ_Number" at 2793.5,-655.67 h60
  text "REV:" at 3638,-655.67 h60
  text ".PCB_Rev" at 3929.5,-655.67 h60
  text "SVN REV:" at 4476,-655.67 h60
  text ".VersionControl_RevNumber" at 4982,-655.67 h60
  text "LAYER NAME =" at -228.5,-858.49 h60
  text "PLOT NAME =" at -228.5,-1064.34 h60
  text ".plot_File_Name" at 577,-1064.34 h60
  text "GENERATED    :" at 2250,-1064.34 h60
  text ".Print_Date" at 3119.5,-1064.34 h60
  text ".Print_Time" at 3848.5,-1064.34 h60
  text "TEXAS INSTRUMENTS" at 5113,-1064.34 h60
M12 Stackup:
  lines w5: 11359,7685.5 14234,7685.5 ; 11359,7780.7 14234,7780.7 ; 11299,6955 ccw(c11330,6955) 11330,6924 14263,6924 ccw(c14263,6955) 14294,6955 14294,7905 ccw(c14263,7905) 14263,7936 11330,7936 ccw(c11330,7905) 11299,7905 11299,6955
  text "Layer Stack Up Detail for: TIDA-00189_E1.PcbDoc" at 11359,7812.85 h60
  text "Layer" at 11359,7745.2 h22
  text "Gerber" at 12080.45,7745.2 h22
  text "Copper" at 12372.95,7745.2 h22
  text "Dielectric" at 12701.36,7745.2 h22
  text "Dielectric" at 13045.17,7745.2 h22
  text "Dielectric" at 13482.55,7745.2 h22
  text "Dielectric" at 13826.36,7745.2 h22
  text "Name" at 11359,7701.2 h22
  text "Document" at 12080.45,7701.2 h22
  text "Thickness" at 12372.95,7701.2 h22
  text "Height" at 12701.36,7701.2 h22
  text "Material" at 13045.17,7701.2 h22
  text "Constant" at 13482.55,7701.2 h22
  text "Type" at 13826.36,7701.2 h22
  text "Top Solder Mask" at 11359,7630.29 h31
  text "(.GTS)" at 12080.45,7630.29 h31
  text "0.4mil" at 12701.36,7630.29 h31
  text "Solder Resist" at 13045.17,7630.29 h31
  text "3.50" at 13482.55,7630.29 h31
  text "Layer 1 - Top Layer" at 11359,7524.88 h31
  text "(.GTL)" at 12080.45,7524.88 h31
  text "1.4mil" at 12372.95,7524.88 h31
  text "18.6mil" at 12701.36,7472.17 h31
  text "370HR" at 13045.17,7472.17 h31
  text "4.80" at 13482.55,7472.17 h31
  text "Core" at 13826.36,7472.17 h31
  text "Layer 2 - GND" at 11359,7419.46 h31
  text "(.G1)" at 12080.45,7419.46 h31
  text "1.4mil" at 12372.95,7419.46 h31
  text "18.6mil" at 12701.36,7366.75 h31
  text "370HR" at 13045.17,7366.75 h31
  text "4.80" at 13482.55,7366.75 h31
  text "PrePreg" at 13826.36,7366.75 h31
  text "Layer 3 - Inner Layer" at 11359,7314.04 h31
  text "(.G2)" at 12080.45,7314.04 h31
  text "1.4mil" at 12372.95,7314.04 h31
  text "18.6mil" at 12701.36,7261.33 h31
  text "370HR" at 13045.17,7261.33 h31
  text "4.80" at 13482.55,7261.33 h31
  text "Core" at 13826.36,7261.33 h31
  text "Layer 4 - Bottom Layer" at 11359,7208.63 h31
  text "(.GBL)" at 12080.45,7208.63 h31
  text "1.4mil" at 12372.95,7208.63 h31
  text "Bottom Solder Mask" at 11359,7103.21 h31
  text "(.GBS)" at 12080.45,7103.21 h31
  text "0.4mil" at 12701.36,7103.21 h31
  text "Solder Resist" at 13045.17,7103.21 h31
  text "3.50" at 13482.55,7103.21 h31
  text ".Layer_Name" at 577,-858.49 h60
M13 Component Bodies Top:
  text ".Layer_Name" at 577,-858.49 h60
M14 Component Bodies Bottom:
  text ".Layer_Name" at 577,-858.49 h60
M15 Courtyards Top:
  text ".Layer_Name" at 577,-858.49 h60
M16 Courtyards Bottom:
  text ".Layer_Name" at 577,-858.49 h60
Drill Drawing:
  text ".legend" at 5122.5,725.5 h60
  text "Drill Table" at 5147.5,540.5 h60
  text ".Layer_Name" at 577,-858.49 h60

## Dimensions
0,0 to 2350,0 on M2 Board Dimensions
0,0 to 0,1950 on M2 Board Dimensions
975,975 to 830,2205 on M2 Board Dimensions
